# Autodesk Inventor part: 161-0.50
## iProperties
Created: 2007-06
Part Number: 161-0.50
Document SubType Name: Modeling
Designer: btaylor
Density: 1 g/cm^3
Author: btaylor
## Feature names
1. Extrusion1
2. Extrusion2
3. Extrusion3
4. Extrusion4
5. Extrusion5
6. Fillet1
7. Fillet2
8. Fillet3
9. Fillet4
10. Fillet5
11. Fillet6
12. Extrusion6
13. Extrusion7
14. Extrusion8
15. Extrusion9
16. Extrusion10
17. Fillet7
18. Fillet8
19. Fillet9
20. Fillet10
21. Fillet11
22. Chamfer1
23. Chamfer2
24. Chamfer3
25. Fillet12
26. Fillet13
27. Fillet14
